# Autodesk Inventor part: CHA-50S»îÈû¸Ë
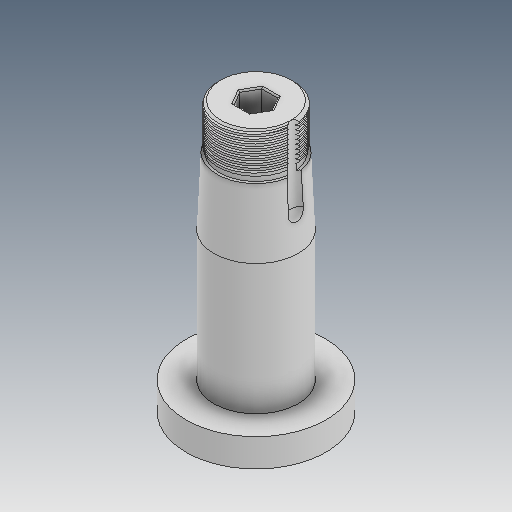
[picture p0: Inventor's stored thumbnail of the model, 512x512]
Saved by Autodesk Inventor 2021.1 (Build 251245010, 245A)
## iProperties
Created: 2019-12
Part Number: CHA-50S»îÈû¸Ë
Material: Ogólny
Document SubType Name: Modeling
Designer: user
Density: 1 g/cm^3
Appearance: Domyślna
Author: user
Revision Number: ÈÎºÎ
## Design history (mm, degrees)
feature "ÊäÈë1"
node "Bryła1"
